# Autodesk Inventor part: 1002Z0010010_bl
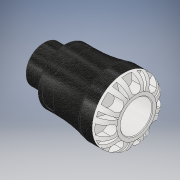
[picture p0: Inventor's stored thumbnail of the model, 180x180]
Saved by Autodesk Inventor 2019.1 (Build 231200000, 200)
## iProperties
Created: 2016-12
Part Number: 1002Z0010010_bl
Material: PVC-Piping
Description: PLASSON MALE ADAPTOR 1''CTS x 1''NPT SERIES 1
Document SubType Name: Modeling
Designer: KIM
Mass: 61.7504 g
Surface Area: 140.097 cm^2
Volume: 44.1074 cm^3
Density: 1.4 g/cm^3
Appearance: Black Cast
Author: KIM
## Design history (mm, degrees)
derived "1002Z.ipt"
feature "Solid1::1002Z.ipt" dims "ScaleForDerivedMember" = 10
tag "TaggingFeature1"
body "Solid1"
other parameters: "d0" = 84.074 [user parameter], "d1" = 22.72284 [user parameter], "d2" = 28.45 [user parameter], "d3" = 35.5625 [user parameter], "d4" = 57.912 [user parameter], "d6" = 54.102 [user parameter], "d8" = 49.2252 [user parameter], "d13" = 8.9398 [user parameter], "d14" = 8.9398 [user parameter], "d15" = 0 [user parameter], "d17" = 360 deg [user parameter], "d19" = 8 deg [user parameter], "d20" = 0.569 [user parameter], "d21" = 0.569 [user parameter], "d22" = 8 deg [user parameter], "d24" = 0 [user parameter], "d26" = 360 deg [user parameter], "d32" = 0.925 [user parameter], "d33" = 5.7912 [user parameter], "d34" = 33.249 [user parameter], "d35" = 5.69 [user parameter], "d38" = 19.05 [user parameter], "d39" = 0.99747 [user parameter], "d42" = 9.9575 [user parameter], "d43" = 6.5435 [user parameter], "d45" = 17.52201 [user parameter], "d46" = 0 [user parameter], "d59" = 360 deg [user parameter], "d61" = 8.46387 [user parameter], "d62" = 0.569 [user parameter], "d64" = 0 [user parameter], "d65" = 0.57912 [user parameter], "d_" = 28.45 [user parameter], "E_" = 57.912 [user parameter], "H_" = 84.074 [user parameter], "l_" = 54.102 [user parameter], "R_" = 33.249 [user parameter], "l_2" = 19.05 [user parameter], "d9" = 11.17475 [user parameter], "d11" = 57.912 [user parameter], "d12" = 35.5625 [user parameter]
